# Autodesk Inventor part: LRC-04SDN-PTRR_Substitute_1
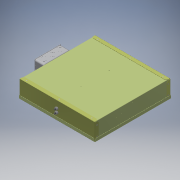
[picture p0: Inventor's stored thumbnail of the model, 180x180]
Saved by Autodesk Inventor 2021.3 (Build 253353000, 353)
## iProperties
Part Number: LRC-04SDN-PTRR_Substitute_1
Material: Generic
Document SubType Name: Modeling
Designer: JChurch
Manufacturer: Standard
Standards Organization: Custom
Density: 1 g/cm^3
Appearance: Smooth - Black
Author: JChurch
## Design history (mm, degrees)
derived "LRC-04SDN-PTRR.iam"
body "Solid9"
node "830520-00-00.ipt:1"
node "885000-00-00.iam:1::830000-00-00.ipt:1"
body "Solid10"
node "885000-00-00.iam:1::509424-00-00.ipt:1"
body "Solid11"
node "885000-00-00.iam:1::830593-00-00.ipt:1"
body "Solid12"
node "885000-00-00.iam:1::506002-00-00.ipt:1"
body "Solid13"
node "885000-00-00.iam:1::506002-00-00.ipt:2"
body "Solid14"
node "885000-00-00.iam:1::506002-00-00.ipt:3"
body "Solid15"
node "885000-00-00.iam:1::506002-00-00.ipt:4"
body "Solid16"
node "885000-00-00.iam:1::506002-00-00.ipt:5"
body "Solid17"
node "885000-00-00.iam:1::506002-00-00.ipt:6"
body "Solid18"
node "885000-00-00.iam:1::506002-00-00.ipt:7"
body "Solid19"
node "885000-00-00.iam:1::506002-00-00.ipt:8"
body "Solid20"
node "885000-00-00.iam:1::506002-00-00.ipt:9"
body "Solid21"
node "885000-00-00.iam:1::506002-00-00.ipt:10"
body "Solid22"
node "885000-00-00.iam:1::506002-00-00.ipt:11"
body "Solid23"
node "885000-00-00.iam:1::506002-00-00.ipt:12"
body "Solid24"
node "885000-00-00.iam:1::506002-00-00.ipt:13"
body "Solid25"
node "885000-00-00.iam:1::506002-00-00.ipt:14"
body "Solid26"
node "885000-00-00.iam:1::500027-00-00.ipt:1"
body "Solid27"
node "885000-00-00.iam:1::500027-00-00.ipt:2"
body "Solid28"
node "885000-00-00.iam:1::502116-00-00.ipt:1"
body "Solid29"
node "885000-00-00.iam:1::502116-00-00.ipt:2"
body "Solid30"
node "885000-00-00.iam:1::501030-00-00.ipt:1"
body "Solid31"
node "885000-00-00.iam:1::501030-00-00.ipt:2"
body "Solid32"
node "885000-00-00.iam:1::501030-00-00.ipt:3"
body "Solid33"
node "885000-00-00.iam:1::501030-00-00.ipt:4"
body "Solid34"
node "885000-00-00.iam:1::500027-00-00.ipt:3"
body "Solid35"
node "885000-00-00.iam:1::500027-00-00.ipt:4"
body "Solid36"
node "885000-00-00.iam:1::501030-00-00.ipt:5"
body "Solid37"
node "885000-00-00.iam:1::500027-00-00.ipt:5"
body "Solid38"
node "885000-00-00.iam:1::501030-00-00.ipt:6"
body "Solid39"
node "885000-00-00.iam:1::500027-00-00.ipt:6"
body "Solid40"
node "885000-00-00.iam:1::830593-00-00.ipt:2"
body "Solid41"
node "885000-00-00.iam:1::507032-00-00.ipt:1"
body "Solid42"
node "885000-00-00.iam:1::640042-00-03.ipt:1"
body "Solid43"
node "885000-00-00.iam:1::501030-00-00.ipt:9"
body "Solid44"
node "885000-00-00.iam:1::501030-00-00.ipt:10"
body "Solid45"
node "885000-00-00.iam:1::501030-00-00.ipt:11"
body "Solid46"
node "885000-00-00.iam:1::501030-00-00.ipt:12"
body "Solid47"
node "885000-00-00.iam:1::503031-00-00.ipt:1"
body "Solid48"
node "885000-00-00.iam:1::503031-00-00.ipt:2"
body "Solid49"
node "885000-00-00.iam:1::509425-00-00.ipt:1"
body "Solid50"
node "750472-00-00.iam:1::740103-00-00.ipt:1"
body "Solid51"
node "750472-00-00.iam:1::507035-01-38.ipt:1"
body "Solid52"
node "750472-00-00.iam:1::502055-00-00.ipt:1"
body "Solid53"
node "750472-00-00.iam:1::507035-01-38.ipt:2"
body "Solid54"
node "750472-00-00.iam:1::502055-00-00.ipt:2"
body "Solid55"
node "750472-00-00.iam:1::502060-00-00.ipt:1"
body "Solid56"
node "750472-00-00.iam:1::510051-00-00.ipt:1"
body "Solid57"
node "750472-00-00.iam:1::502060-00-00.ipt:2"
body "Solid58"
node "750472-00-00.iam:1::502060-00-00.ipt:3"
body "Solid59"
node "750472-00-00.iam:1::502060-00-00.ipt:4"
body "Solid60"
node "725383-00-00.ipt:1"
body "Solid61"
node "501087-00-00.ipt:1"
body "Solid62"
node "501087-00-00.ipt:2"
body "Solid63"
node "501087-00-00.ipt:3"
body "Solid64"
node "501087-00-00.ipt:4"
body "Solid65"
other parameters: "d15" = 61.595, "d16" = 9.525, "d17" = 9.525, "d35" = 5.08
